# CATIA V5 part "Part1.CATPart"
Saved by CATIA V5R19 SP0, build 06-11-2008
Part number: Part1
Bounding box of the stored display mesh (mm): x -91.799 to 91.799, y 0 to 106, z -106 to 106
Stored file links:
  D:\AUTO BATCH (BHEL)\Hexagonal Dome\Part1.CATPart
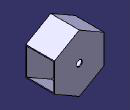
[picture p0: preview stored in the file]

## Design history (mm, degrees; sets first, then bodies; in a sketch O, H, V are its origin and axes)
Set1
  Sketch1 on zx-plane, origin (0, 0, 0), H (-1, 0, 0), V (0, 0, 1)
    point P1 (91.7987, -53)
    point P2 (91.7987, 53)
    point P3 (0, 106)
    point P4 (-91.7987, 53)
    point P5 (-91.7987, -53)
    point P6 (0, -106)
    point P7 (91.7987, 0)
    line L1 (91.7987, -53) -> (91.7987, 53)
    line L2 (91.7987, 53) -> (0, 106)
    line L3 (0, 106) -> (-91.7987, 53)
    line L4 (-91.7987, 53) -> (-91.7987, -53)
    line L5 (-91.7987, -53) -> (0, -106)
    line L6 (0, -106) -> (91.7987, -53)
    construction line L7 (0, 0) -> (91.7987, 0)
    construction circle A1 centre (0, 0) radius 106
    construction arc A2 centre (-91.7987, -53) radius 106 from (-91.7987, 53) to (0, -106) cw
    construction arc A3 centre (91.7987, 53) radius 106 from (0, 106) to (91.7987, -53) ccw
    length L1 = 106
    horizontal: L7 H
    coincidence: A1 P1, A1 P2, A1 P3, A1 P4, A1 P5, A1 P6, A2 O, A3 O
    midpoint: P7 L1
Body1 (main body)
  Pad1: profile Sketch1, direction (0, 1, 0), length 106
  Shell1: ExtOffset 0, IntOffset 3, Face (face of Pad1 from Sketch1.L4; face of Pad1 from Sketch1.L1)
  Sketch2 on start face of Pad1, origin (0, 0, 0), H (1, 0, 0), V (0, 0, 1)
    circle A1 centre (0, 0) radius 11.1
    radius A1 = 11.1
  Pocket1: profile Sketch2, direction (0, 1, 0), length 150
